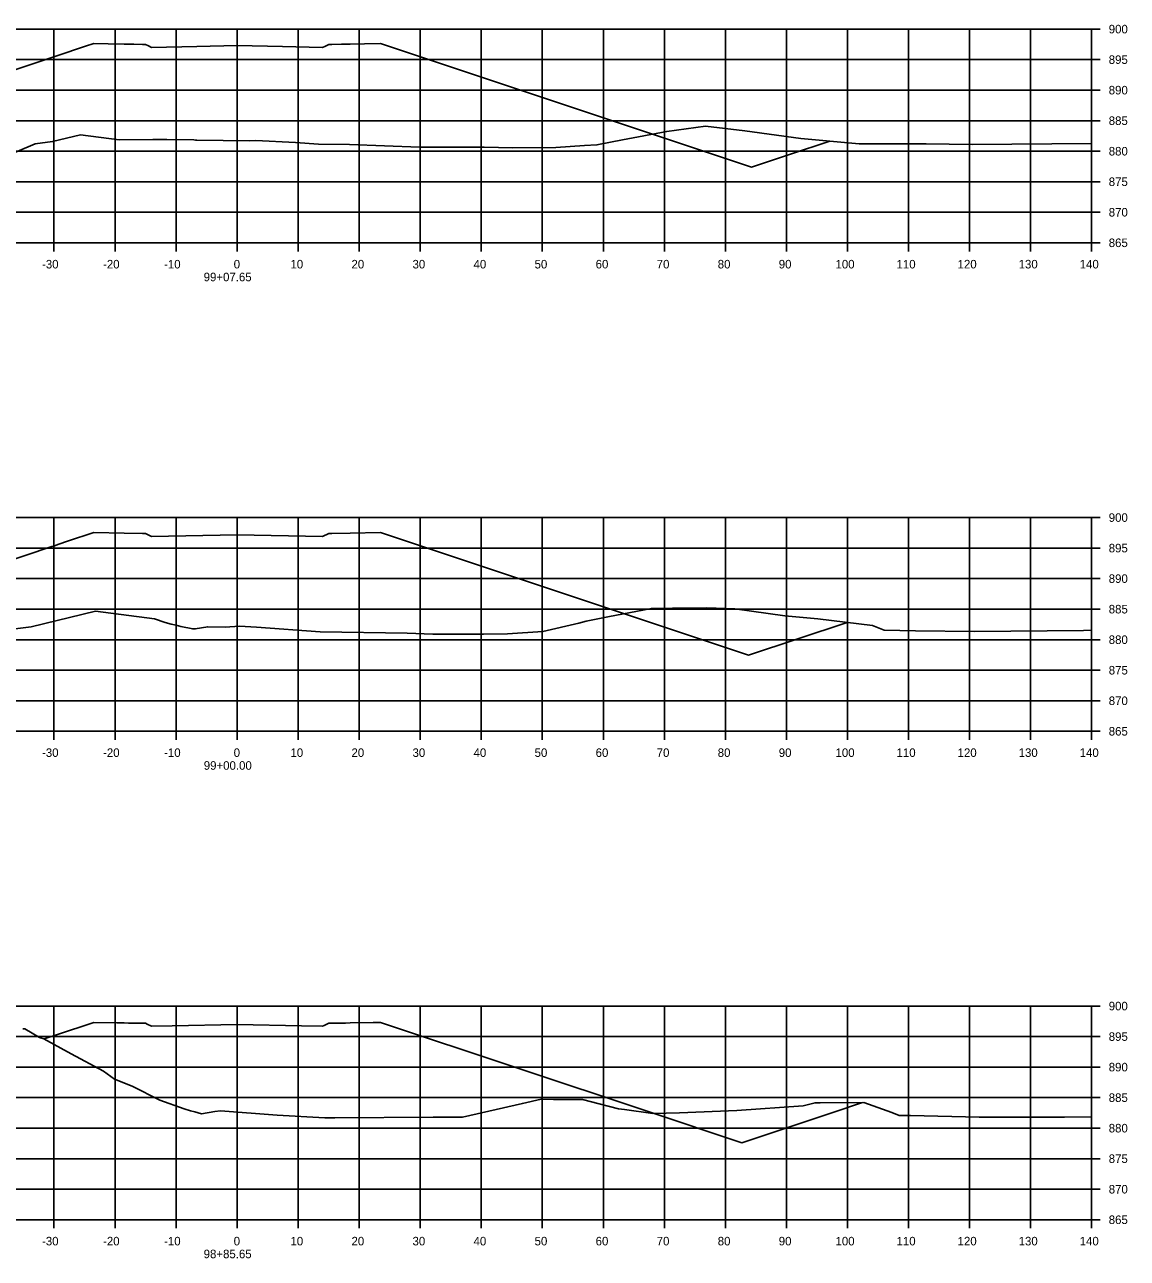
# Model space of a CAD drawing. Extents: x 1098669 to 1198896, y 698679 to 704410.
# Drawn here: x 1113464.1 to 1113644.7, y 701992.2 to 702194.3 of the extents above; entities that cross this region are included whole.
import ezdxf

# ---------------------------------------------------------------- set-up
doc = ezdxf.new("R2010")
doc.units = 0
for name, color, linetype in [('R_Alt Surface', 7, 'Continuous'), ('R_Axis', 7, 'Continuous'), ('R_Axis Annot', 7, 'Continuous'), ('R_Fin Surface', 7, 'Continuous'), ('R_Grid', 7, 'Continuous')]:
    doc.layers.add(name, color=color, linetype=linetype)

msp = doc.modelspace()

# ---------------------------------------------------------------- linework, layer by layer
at = {"layer": 'R_Alt Surface'}
for points in [[(1113459.47, 702172.09), (1113465.81, 702174.79), (1113468.65, 702175.14), (1113473.21, 702176.23), (1113479.57, 702175.41), (1113485.05, 702175.49), (1113487.38, 702175.48), (1113491.79, 702175.41), (1113492.08, 702175.38), (1113492.24, 702175.38), (1113492.27, 702175.39), (1113500.92, 702175.27), (1113501.96, 702175.34), (1113508.45, 702175), (1113512.18, 702174.73), (1113517.27, 702174.65), (1113528.73, 702174.25), (1113539.35, 702174.21), (1113544.05, 702174.09), (1113551.1, 702174.18), (1113555.76, 702174.49), (1113557.83, 702174.58), (1113562.02, 702175.41), (1113569.26, 702176.81), (1113575.62, 702177.64), (1113582.06, 702176.91), (1113591.22, 702175.62), (1113600.77, 702174.79), (1113605.06, 702174.76), (1113611.75, 702174.75), (1113619.28, 702174.64), (1113638.87, 702174.84)], [(1113458.5, 702094.86), (1113465.11, 702095.69), (1113475.67, 702098.21), (1113485.35, 702096.96), (1113487.11, 702096.39), (1113488.04, 702096.11), (1113488.88, 702095.95), (1113489.64, 702095.72), (1113491.59, 702095.32), (1113492.02, 702095.33), (1113494.05, 702095.67), (1113496.93, 702095.63), (1113499.28, 702095.77), (1113502.07, 702095.62), (1113512.5, 702094.87), (1113526.73, 702094.64), (1113530.96, 702094.49), (1113539.22, 702094.46), (1113543.19, 702094.52), (1113548.97, 702094.89), (1113554.83, 702096.24), (1113556.04, 702096.6), (1113559.58, 702097.3), (1113566.75, 702098.69), (1113570.19, 702098.71), (1113575.82, 702098.77), (1113580.44, 702098.59), (1113588.6, 702097.44), (1113594, 702096.97), (1113602.98, 702095.9), (1113604.9, 702095.13), (1113610.01, 702095.03), (1113619.67, 702094.89), (1113637.55, 702095.07), (1113638.87, 702095.11)], [(1113463.79, 702029.84), (1113464.1, 702029.84), (1113466.5, 702028.41), (1113467.2, 702028.21), (1113471.68, 702025.76), (1113476.98, 702022.9), (1113478.78, 702021.57), (1113481.67, 702020.42), (1113486.19, 702018.14), (1113490.17, 702016.7), (1113491.22, 702016.38), (1113491.92, 702016.25), (1113493.01, 702015.92), (1113495.24, 702016.28), (1113496.13, 702016.38), (1113505.43, 702015.69), (1113513.26, 702015.24), (1113514.87, 702015.23), (1113530.97, 702015.35), (1113535.81, 702015.38), (1113545.61, 702017.61), (1113548.69, 702018.29), (1113550.73, 702018.28), (1113555.44, 702018.27), (1113558.18, 702017.53), (1113561.36, 702016.74), (1113562.35, 702016.62), (1113566.96, 702015.95), (1113571.33, 702016.09), (1113580.73, 702016.43), (1113591.6, 702017.24), (1113593.55, 702017.73), (1113594.38, 702017.73), (1113601.55, 702017.78), (1113606.14, 702016.13), (1113607.32, 702015.66), (1113609.22, 702015.62), (1113620.42, 702015.37), (1113634.43, 702015.36), (1113638.87, 702015.44)]]:
    msp.add_lwpolyline(points, dxfattribs=at)
at = {"layer": 'R_Axis'}
for p, q in [((1113638.87, 702158.56), (1113638.87, 702193.56)), ((1113640.27, 702193.56), (1113638.87, 702193.56)), ((1113640.27, 702188.56), (1113638.87, 702188.56)), ((1113640.27, 702183.56), (1113638.87, 702183.56)), ((1113640.27, 702178.56), (1113638.87, 702178.56)), ((1113640.27, 702173.56), (1113638.87, 702173.56)), ((1113640.27, 702168.56), (1113638.87, 702168.56)), ((1113640.27, 702163.56), (1113638.87, 702163.56)), ((1113358.87, 702158.56), (1113638.87, 702158.56)), ((1113468.87, 702157.16), (1113468.87, 702158.56)), ((1113478.87, 702157.16), (1113478.87, 702158.56)), ((1113488.87, 702157.16), (1113488.87, 702158.56)), ((1113498.87, 702157.16), (1113498.87, 702158.56)), ((1113508.87, 702157.16), (1113508.87, 702158.56)), ((1113518.87, 702157.16), (1113518.87, 702158.56)), ((1113528.87, 702157.16), (1113528.87, 702158.56)), ((1113538.87, 702157.16), (1113538.87, 702158.56)), ((1113548.87, 702157.16), (1113548.87, 702158.56)), ((1113558.87, 702157.16), (1113558.87, 702158.56)), ((1113568.87, 702157.16), (1113568.87, 702158.56)), ((1113578.87, 702157.16), (1113578.87, 702158.56)), ((1113588.87, 702157.16), (1113588.87, 702158.56)), ((1113598.87, 702157.16), (1113598.87, 702158.56)), ((1113608.87, 702157.16), (1113608.87, 702158.56)), ((1113618.87, 702157.16), (1113618.87, 702158.56)), ((1113628.87, 702157.16), (1113628.87, 702158.56)), ((1113638.87, 702157.16), (1113638.87, 702158.56)), ((1113640.27, 702158.56), (1113638.87, 702158.56)), ((1113638.87, 702078.56), (1113638.87, 702113.56)), ((1113640.27, 702113.56), (1113638.87, 702113.56)), ((1113640.27, 702108.56), (1113638.87, 702108.56)), ((1113640.27, 702103.56), (1113638.87, 702103.56)), ((1113640.27, 702098.56), (1113638.87, 702098.56)), ((1113640.27, 702093.56), (1113638.87, 702093.56)), ((1113640.27, 702088.56), (1113638.87, 702088.56)), ((1113640.27, 702083.56), (1113638.87, 702083.56)), ((1113358.87, 702078.56), (1113638.87, 702078.56)), ((1113468.87, 702077.16), (1113468.87, 702078.56)), ((1113478.87, 702077.16), (1113478.87, 702078.56)), ((1113488.87, 702077.16), (1113488.87, 702078.56)), ((1113498.87, 702077.16), (1113498.87, 702078.56)), ((1113508.87, 702077.16), (1113508.87, 702078.56)), ((1113518.87, 702077.16), (1113518.87, 702078.56)), ((1113528.87, 702077.16), (1113528.87, 702078.56)), ((1113538.87, 702077.16), (1113538.87, 702078.56)), ((1113548.87, 702077.16), (1113548.87, 702078.56)), ((1113558.87, 702077.16), (1113558.87, 702078.56)), ((1113568.87, 702077.16), (1113568.87, 702078.56)), ((1113578.87, 702077.16), (1113578.87, 702078.56)), ((1113588.87, 702077.16), (1113588.87, 702078.56)), ((1113598.87, 702077.16), (1113598.87, 702078.56)), ((1113608.87, 702077.16), (1113608.87, 702078.56)), ((1113618.87, 702077.16), (1113618.87, 702078.56)), ((1113628.87, 702077.16), (1113628.87, 702078.56)), ((1113638.87, 702077.16), (1113638.87, 702078.56)), ((1113640.27, 702078.56), (1113638.87, 702078.56)), ((1113638.87, 701998.56), (1113638.87, 702033.56)), ((1113640.27, 702033.56), (1113638.87, 702033.56)), ((1113640.27, 702028.56), (1113638.87, 702028.56)), ((1113640.27, 702023.56), (1113638.87, 702023.56)), ((1113640.27, 702018.56), (1113638.87, 702018.56)), ((1113640.27, 702013.56), (1113638.87, 702013.56)), ((1113640.27, 702008.56), (1113638.87, 702008.56)), ((1113640.27, 702003.56), (1113638.87, 702003.56)), ((1113358.87, 701998.56), (1113638.87, 701998.56)), ((1113468.87, 701997.16), (1113468.87, 701998.56)), ((1113478.87, 701997.16), (1113478.87, 701998.56)), ((1113488.87, 701997.16), (1113488.87, 701998.56)), ((1113498.87, 701997.16), (1113498.87, 701998.56)), ((1113508.87, 701997.16), (1113508.87, 701998.56)), ((1113518.87, 701997.16), (1113518.87, 701998.56)), ((1113528.87, 701997.16), (1113528.87, 701998.56)), ((1113538.87, 701997.16), (1113538.87, 701998.56)), ((1113548.87, 701997.16), (1113548.87, 701998.56)), ((1113558.87, 701997.16), (1113558.87, 701998.56)), ((1113568.87, 701997.16), (1113568.87, 701998.56)), ((1113578.87, 701997.16), (1113578.87, 701998.56)), ((1113588.87, 701997.16), (1113588.87, 701998.56)), ((1113598.87, 701997.16), (1113598.87, 701998.56)), ((1113608.87, 701997.16), (1113608.87, 701998.56)), ((1113618.87, 701997.16), (1113618.87, 701998.56)), ((1113628.87, 701997.16), (1113628.87, 701998.56)), ((1113638.87, 701997.16), (1113638.87, 701998.56)), ((1113640.27, 701998.56), (1113638.87, 701998.56))]:
    msp.add_line(p, q, dxfattribs=at)
at = {"layer": 'R_Fin Surface'}
for points in [[(1113448.51, 702182.23), (1113471.13, 702189.78), (1113472.22, 702190.15), (1113474.02, 702190.76), (1113475.37, 702191.21), (1113477.72, 702191.16), (1113480.37, 702191.11), (1113481.96, 702191.07), (1113483.37, 702191.05), (1113483.6, 702191.05), (1113483.87, 702191.05), (1113484.34, 702190.82), (1113484.87, 702190.57), (1113492.29, 702190.71), (1113498.87, 702190.85), (1113506.29, 702190.7), (1113512.87, 702190.57), (1113513.34, 702190.79), (1113513.87, 702191.05), (1113514.1, 702191.05), (1113514.37, 702191.05), (1113515.96, 702191.08), (1113517.37, 702191.11), (1113519.72, 702191.15), (1113522.37, 702191.21), (1113550.86, 702181.71), (1113583.17, 702170.94), (1113589.35, 702173), (1113595.98, 702175.2)], [(1113389.33, 702082.42), (1113456.55, 702104.82), (1113458.27, 702105.39), (1113459.57, 702105.82), (1113468.51, 702108.81), (1113468.94, 702108.95), (1113469.65, 702109.19), (1113471.08, 702109.67), (1113475.37, 702111.1), (1113480.37, 702111), (1113483.37, 702110.94), (1113483.87, 702110.94), (1113484.87, 702110.46), (1113498.87, 702110.74), (1113512.87, 702110.46), (1113513.87, 702110.94), (1113514.37, 702110.94), (1113517.37, 702111), (1113522.37, 702111.1), (1113582.64, 702091.01), (1113598.79, 702096.4)], [(1113467.25, 702028.18), (1113469.29, 702028.86), (1113475.37, 702030.89), (1113479.15, 702030.81), (1113480.37, 702030.79), (1113481.09, 702030.77), (1113483.37, 702030.73), (1113483.75, 702030.73), (1113483.87, 702030.73), (1113484.11, 702030.61), (1113484.87, 702030.25), (1113488.22, 702030.31), (1113498.87, 702030.53), (1113509.43, 702030.32), (1113512.87, 702030.25), (1113513.11, 702030.36), (1113513.87, 702030.73), (1113514.25, 702030.73), (1113514.37, 702030.73), (1113516.64, 702030.77), (1113517.37, 702030.79), (1113521.15, 702030.86), (1113522.37, 702030.89), (1113566.52, 702016.17), (1113581.56, 702011.16), (1113596.49, 702016.13), (1113601.35, 702017.75)]]:
    msp.add_lwpolyline(points, dxfattribs=at)
at = {"layer": 'R_Grid'}
for p, q in [((1113358.87, 702193.56), (1113638.87, 702193.56)), ((1113468.87, 702158.56), (1113468.87, 702193.56)), ((1113478.87, 702158.56), (1113478.87, 702193.56)), ((1113488.87, 702158.56), (1113488.87, 702193.56)), ((1113498.87, 702158.56), (1113498.87, 702193.56)), ((1113508.87, 702158.56), (1113508.87, 702193.56)), ((1113518.87, 702158.56), (1113518.87, 702193.56)), ((1113528.87, 702158.56), (1113528.87, 702193.56)), ((1113538.87, 702158.56), (1113538.87, 702193.56)), ((1113548.87, 702158.56), (1113548.87, 702193.56)), ((1113558.87, 702158.56), (1113558.87, 702193.56)), ((1113568.87, 702158.56), (1113568.87, 702193.56)), ((1113578.87, 702158.56), (1113578.87, 702193.56)), ((1113588.87, 702158.56), (1113588.87, 702193.56)), ((1113598.87, 702158.56), (1113598.87, 702193.56)), ((1113608.87, 702158.56), (1113608.87, 702193.56)), ((1113618.87, 702158.56), (1113618.87, 702193.56)), ((1113628.87, 702158.56), (1113628.87, 702193.56)), ((1113638.87, 702158.56), (1113638.87, 702193.56)), ((1113358.87, 702188.56), (1113638.87, 702188.56)), ((1113358.87, 702183.56), (1113638.87, 702183.56)), ((1113358.87, 702178.56), (1113638.87, 702178.56)), ((1113358.87, 702173.56), (1113638.87, 702173.56)), ((1113358.87, 702168.56), (1113638.87, 702168.56)), ((1113358.87, 702163.56), (1113638.87, 702163.56)), ((1113358.87, 702158.56), (1113638.87, 702158.56)), ((1113358.87, 702113.56), (1113638.87, 702113.56)), ((1113468.87, 702078.56), (1113468.87, 702113.56)), ((1113478.87, 702078.56), (1113478.87, 702113.56)), ((1113488.87, 702078.56), (1113488.87, 702113.56)), ((1113498.87, 702078.56), (1113498.87, 702113.56)), ((1113508.87, 702078.56), (1113508.87, 702113.56)), ((1113518.87, 702078.56), (1113518.87, 702113.56)), ((1113528.87, 702078.56), (1113528.87, 702113.56)), ((1113538.87, 702078.56), (1113538.87, 702113.56)), ((1113548.87, 702078.56), (1113548.87, 702113.56)), ((1113558.87, 702078.56), (1113558.87, 702113.56)), ((1113568.87, 702078.56), (1113568.87, 702113.56)), ((1113578.87, 702078.56), (1113578.87, 702113.56)), ((1113588.87, 702078.56), (1113588.87, 702113.56)), ((1113598.87, 702078.56), (1113598.87, 702113.56)), ((1113608.87, 702078.56), (1113608.87, 702113.56)), ((1113618.87, 702078.56), (1113618.87, 702113.56)), ((1113628.87, 702078.56), (1113628.87, 702113.56)), ((1113638.87, 702078.56), (1113638.87, 702113.56)), ((1113358.87, 702108.56), (1113638.87, 702108.56)), ((1113358.87, 702103.56), (1113638.87, 702103.56)), ((1113358.87, 702098.56), (1113638.87, 702098.56)), ((1113358.87, 702093.56), (1113638.87, 702093.56)), ((1113358.87, 702088.56), (1113638.87, 702088.56)), ((1113358.87, 702083.56), (1113638.87, 702083.56)), ((1113358.87, 702078.56), (1113638.87, 702078.56)), ((1113358.87, 702033.56), (1113638.87, 702033.56)), ((1113468.87, 701998.56), (1113468.87, 702033.56)), ((1113478.87, 701998.56), (1113478.87, 702033.56)), ((1113488.87, 701998.56), (1113488.87, 702033.56)), ((1113498.87, 701998.56), (1113498.87, 702033.56)), ((1113508.87, 701998.56), (1113508.87, 702033.56)), ((1113518.87, 701998.56), (1113518.87, 702033.56)), ((1113528.87, 701998.56), (1113528.87, 702033.56)), ((1113538.87, 701998.56), (1113538.87, 702033.56)), ((1113548.87, 701998.56), (1113548.87, 702033.56)), ((1113558.87, 701998.56), (1113558.87, 702033.56)), ((1113568.87, 701998.56), (1113568.87, 702033.56)), ((1113578.87, 701998.56), (1113578.87, 702033.56)), ((1113588.87, 701998.56), (1113588.87, 702033.56)), ((1113598.87, 701998.56), (1113598.87, 702033.56)), ((1113608.87, 701998.56), (1113608.87, 702033.56)), ((1113618.87, 701998.56), (1113618.87, 702033.56)), ((1113628.87, 701998.56), (1113628.87, 702033.56)), ((1113638.87, 701998.56), (1113638.87, 702033.56)), ((1113358.87, 702028.56), (1113638.87, 702028.56)), ((1113358.87, 702023.56), (1113638.87, 702023.56)), ((1113358.87, 702018.56), (1113638.87, 702018.56)), ((1113358.87, 702013.56), (1113638.87, 702013.56)), ((1113358.87, 702008.56), (1113638.87, 702008.56)), ((1113358.87, 702003.56), (1113638.87, 702003.56)), ((1113358.87, 701998.56), (1113638.87, 701998.56))]:
    msp.add_line(p, q, dxfattribs=at)

# ---------------------------------------------------------------- texts
at = {"layer": 'R_Axis Annot'}
for s, p in [('900', (1113641.67, 702192.86)), ('895', (1113641.67, 702187.86)), ('890', (1113641.67, 702182.86)), ('885', (1113641.67, 702177.86)), ('880', (1113641.67, 702172.86)), ('875', (1113641.67, 702167.86)), ('870', (1113641.67, 702162.86)), ('865', (1113641.67, 702157.86)), ('-30', (1113466.91, 702154.36)), ('-20', (1113476.91, 702154.36)), ('-10', (1113486.91, 702154.36)), ('0', (1113498.31, 702154.36)), ('10', (1113507.61, 702154.36)), ('20', (1113517.61, 702154.36)), ('30', (1113527.61, 702154.36)), ('40', (1113537.61, 702154.36)), ('50', (1113547.61, 702154.36)), ('60', (1113557.61, 702154.36)), ('70', (1113567.61, 702154.36)), ('80', (1113577.61, 702154.36)), ('90', (1113587.61, 702154.36)), ('100', (1113596.91, 702154.36)), ('110', (1113606.91, 702154.36)), ('120', (1113616.91, 702154.36)), ('130', (1113626.91, 702154.36)), ('140', (1113636.91, 702154.36)), ('99+07.65', (1113493.39, 702152.26)), ('900', (1113641.67, 702112.86)), ('895', (1113641.67, 702107.86)), ('890', (1113641.67, 702102.86)), ('885', (1113641.67, 702097.86)), ('880', (1113641.67, 702092.86)), ('875', (1113641.67, 702087.86)), ('870', (1113641.67, 702082.86)), ('865', (1113641.67, 702077.86)), ('-30', (1113466.91, 702074.36)), ('-20', (1113476.91, 702074.36)), ('-10', (1113486.91, 702074.36)), ('0', (1113498.31, 702074.36)), ('10', (1113507.61, 702074.36)), ('20', (1113517.61, 702074.36)), ('30', (1113527.61, 702074.36)), ('40', (1113537.61, 702074.36)), ('50', (1113547.61, 702074.36)), ('60', (1113557.61, 702074.36)), ('70', (1113567.61, 702074.36)), ('80', (1113577.61, 702074.36)), ('90', (1113587.61, 702074.36)), ('100', (1113596.91, 702074.36)), ('110', (1113606.91, 702074.36)), ('120', (1113616.91, 702074.36)), ('130', (1113626.91, 702074.36)), ('140', (1113636.91, 702074.36)), ('99+00.00', (1113493.41, 702072.26)), ('900', (1113641.67, 702032.86)), ('895', (1113641.67, 702027.86)), ('890', (1113641.67, 702022.86)), ('885', (1113641.67, 702017.86)), ('880', (1113641.67, 702012.86)), ('875', (1113641.67, 702007.86)), ('870', (1113641.67, 702002.86)), ('865', (1113641.67, 701997.86)), ('-30', (1113466.91, 701994.36)), ('-20', (1113476.91, 701994.36)), ('-10', (1113486.91, 701994.36)), ('0', (1113498.31, 701994.36)), ('10', (1113507.61, 701994.36)), ('20', (1113517.61, 701994.36)), ('30', (1113527.61, 701994.36)), ('40', (1113537.61, 701994.36)), ('50', (1113547.61, 701994.36)), ('60', (1113557.61, 701994.36)), ('70', (1113567.61, 701994.36)), ('80', (1113577.61, 701994.36)), ('90', (1113587.61, 701994.36)), ('100', (1113596.91, 701994.36)), ('110', (1113606.91, 701994.36)), ('120', (1113616.91, 701994.36)), ('130', (1113626.91, 701994.36)), ('140', (1113636.91, 701994.36)), ('98+85.65', (1113493.39, 701992.26))]:
    msp.add_text(s, height=1.4, dxfattribs=at).set_placement(p)

doc.saveas('drawing.dxf')
